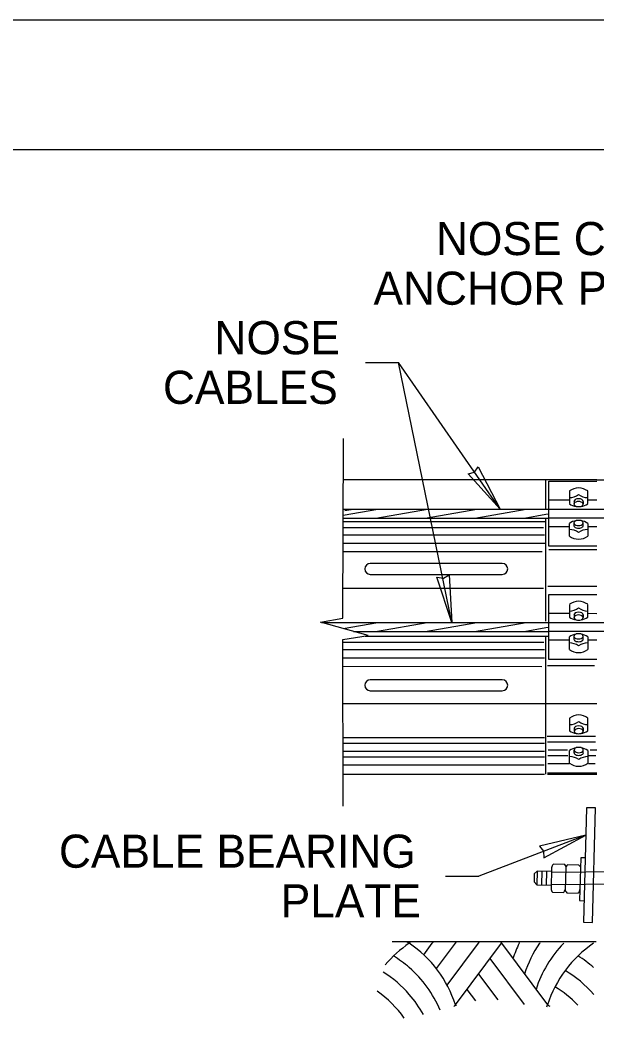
# Model space of a CAD drawing. Extents: x 1312564.2 to 1312581.5, y 1207298.4 to 1207352.6.
# Drawn here: x 1312576.216 to 1312577.61, y 1207335.767 to 1207338.221 of the extents above; entities that cross this region are included whole.
import ezdxf

# ---------------------------------------------------------------- set-up
doc = ezdxf.new("R2010")
doc.units = 0
for name, color, linetype in [('Level 1', 7, 'Continuous'), ('Level 15', 7, 'Continuous'), ('Level 2', 7, 'Continuous'), ('Level 20', 7, 'Continuous'), ('Level 6', 7, 'Continuous')]:
    doc.layers.add(name, color=color, linetype=linetype)

msp = doc.modelspace()

# ---------------------------------------------------------------- linework, layer by layer
at = {"layer": 'Level 1'}
msp.add_line((1312565.4155, 1207337.9084), (1312581.1655, 1207337.9084), dxfattribs=at)
at = {"layer": 'Level 15'}
for p, q in [((1312577.0506, 1207337.393), (1312577.1307, 1207337.393)), ((1312577.2592, 1207336.764), (1312577.1307, 1207337.393)), ((1312577.3766, 1207337.0387), (1312577.1307, 1207337.393)), ((1312577.5832, 1207336.2498), (1312577.3244, 1207336.151)), ((1312577.2443, 1207336.151), (1312577.3244, 1207336.151))]:
    msp.add_line(p, q, dxfattribs=at)
msp.add_lwpolyline([(1312576.9968, 1207336.3197), (1312576.9962, 1207336.723), (1312577.0572, 1207336.7325), (1312576.9417, 1207336.7651), (1312576.9962, 1207336.7749), (1312576.9973, 1207337.2094)], dxfattribs=at)
for points in [[(1312577.3766, 1207337.0387), (1312577.2989, 1207337.1238), (1312577.3141, 1207337.128), (1312577.3233, 1207337.1409)], [(1312577.2592, 1207336.764), (1312577.2232, 1207336.8735), (1312577.2389, 1207336.8711), (1312577.2526, 1207336.8791)], [(1312577.5832, 1207336.2498), (1312577.4711, 1207336.223), (1312577.4814, 1207336.211), (1312577.4818, 1207336.1951)]]:
    msp.add_lwpolyline(points, close=True, dxfattribs=at)
at = {"layer": 'Level 2'}
msp.add_lwpolyline([(1312564.478, 1207327.2209), (1312581.478, 1207327.2209), (1312581.478, 1207338.2209), (1312564.478, 1207338.2209)], close=True, dxfattribs=at)
at = {"layer": 'Level 6'}
for p, q in [((1312577.6098, 1207337.1092), (1312576.997, 1207337.1093)), ((1312577.487, 1207337.0401), (1312577.487, 1207337.1093)), ((1312577.6097, 1207337.1092), (1312577.8224, 1207337.1092)), ((1312577.5438, 1207337.0824), (1312577.5438, 1207337.0663)), ((1312577.5881, 1207337.0663), (1312577.5881, 1207337.0824)), ((1312577.5438, 1207337.0598), (1312577.4939, 1207337.0598)), ((1312577.5438, 1207337.0663), (1312577.5438, 1207337.0517)), ((1312577.5549, 1207337.0571), (1312577.5549, 1207337.0505)), ((1312577.577, 1207337.0571), (1312577.577, 1207337.0505)), ((1312577.5881, 1207337.0517), (1312577.5881, 1207337.0663)), ((1312577.6097, 1207337.0598), (1312577.5881, 1207337.0598)), ((1312576.9968, 1207337.0239), (1312577.0806, 1207337.0387)), ((1312576.9969, 1207337.0387), (1312577.4939, 1207337.0387)), ((1312577.0006, 1207337.0352), (1312577.0208, 1207337.0387)), ((1312577.0755, 1207337.0167), (1312577.2002, 1207337.0387)), ((1312577.1952, 1207337.0167), (1312577.3198, 1207337.0387)), ((1312577.3148, 1207337.0167), (1312577.4395, 1207337.0387)), ((1312577.4939, 1207337.0387), (1312577.9371, 1207337.0387)), ((1312576.9968, 1207337.0167), (1312577.4939, 1207337.0167)), ((1312576.9968, 1207337.0087), (1312577.4859, 1207337.0087)), ((1312577.4344, 1207337.0167), (1312577.487, 1207337.026)), ((1312577.487, 1207337.026), (1312577.4939, 1207337.0272)), ((1312577.487, 1207336.7678), (1312577.487, 1207337.0143)), ((1312577.9371, 1207337.0167), (1312577.4939, 1207337.0167)), ((1312576.9967, 1207336.9937), (1312577.4812, 1207336.9937)), ((1312577.5438, 1207336.9956), (1312577.4939, 1207336.9956)), ((1312577.5438, 1207336.9891), (1312577.5438, 1207337.0038)), ((1312577.5438, 1207336.9731), (1312577.5438, 1207336.9891)), ((1312577.5549, 1207336.9984), (1312577.5549, 1207337.005)), ((1312577.577, 1207336.9984), (1312577.577, 1207337.005)), ((1312577.5881, 1207337.0038), (1312577.5881, 1207336.9891)), ((1312577.6097, 1207336.9956), (1312577.5881, 1207336.9956)), ((1312577.5881, 1207336.9891), (1312577.5881, 1207336.9731)), ((1312576.9967, 1207336.976), (1312577.4832, 1207336.976)), ((1312576.9966, 1207336.9558), (1312577.4842, 1207336.9558)), ((1312577.4779, 1207336.935), (1312576.9966, 1207336.935)), ((1312577.6097, 1207336.94), (1312577.494, 1207336.94)), ((1312577.3814, 1207336.907), (1312577.0623, 1207336.907)), ((1312577.0623, 1207336.8807), (1312577.3814, 1207336.8807)), ((1312577.4808, 1207336.8467), (1312576.9963, 1207336.8468)), ((1312577.6097, 1207336.8511), (1312577.4914, 1207336.8511)), ((1312577.5438, 1207336.8081), (1312577.5438, 1207336.792)), ((1312577.5438, 1207336.792), (1312577.5438, 1207336.7774)), ((1312577.5881, 1207336.792), (1312577.5881, 1207336.8081)), ((1312577.5881, 1207336.7774), (1312577.5881, 1207336.792)), ((1312576.9439, 1207336.7644), (1312577.4939, 1207336.7644)), ((1312576.9964, 1207336.7497), (1312577.0802, 1207336.7644)), ((1312577.0796, 1207336.7432), (1312577.1999, 1207336.7644)), ((1312577.1948, 1207336.7425), (1312577.3195, 1207336.7644)), ((1312577.3144, 1207336.7425), (1312577.4391, 1207336.7644)), ((1312577.5438, 1207336.7856), (1312577.4939, 1207336.7856)), ((1312577.4939, 1207336.7644), (1312577.9371, 1207336.7644)), ((1312577.5549, 1207336.7828), (1312577.5549, 1207336.7762)), ((1312577.577, 1207336.7828), (1312577.577, 1207336.7762)), ((1312577.6097, 1207336.7855), (1312577.5881, 1207336.7856)), ((1312577.0219, 1207336.7425), (1312577.4939, 1207336.7425)), ((1312577.434, 1207336.7425), (1312577.487, 1207336.7518)), ((1312577.487, 1207336.7518), (1312577.4939, 1207336.753)), ((1312577.4939, 1207336.7425), (1312577.4939, 1207336.7425)), ((1312577.9371, 1207336.7425), (1312577.4939, 1207336.7425)), ((1312576.9968, 1207336.7165), (1312577.4822, 1207336.7165)), ((1312577.0502, 1207336.7314), (1312577.4939, 1207336.7314)), ((1312577.487, 1207336.397), (1312577.487, 1207336.7295)), ((1312577.5438, 1207336.7214), (1312577.4939, 1207336.7214)), ((1312577.5438, 1207336.7149), (1312577.5438, 1207336.7295)), ((1312577.5438, 1207336.6988), (1312577.5438, 1207336.7149)), ((1312577.5549, 1207336.7241), (1312577.5549, 1207336.7307)), ((1312577.577, 1207336.7241), (1312577.577, 1207336.7307)), ((1312577.5881, 1207336.7295), (1312577.5881, 1207336.7149)), ((1312577.6097, 1207336.7213), (1312577.5881, 1207336.7214)), ((1312577.5881, 1207336.7149), (1312577.5881, 1207336.6988)), ((1312576.9962, 1207336.6988), (1312577.4832, 1207336.6988)), ((1312576.9962, 1207336.6791), (1312577.4832, 1207336.6791)), ((1312577.4774, 1207336.6573), (1312576.9963, 1207336.6574)), ((1312577.6046, 1207336.6592), (1312577.4908, 1207336.6593)), ((1312577.3814, 1207336.6256), (1312577.0623, 1207336.6256)), ((1312577.0623, 1207336.5993), (1312577.3814, 1207336.5993)), ((1312577.6097, 1207336.5675), (1312576.9964, 1207336.5676)), ((1312577.5441, 1207336.5332), (1312577.5441, 1207336.5171)), ((1312577.5441, 1207336.5171), (1312577.5441, 1207336.5024)), ((1312577.5884, 1207336.5171), (1312577.5884, 1207336.5332)), ((1312577.5884, 1207336.5024), (1312577.5884, 1207336.5171)), ((1312577.5552, 1207336.5079), (1312577.5552, 1207336.5013)), ((1312577.5773, 1207336.5079), (1312577.5773, 1207336.5013)), ((1312577.4832, 1207336.485), (1312576.9966, 1207336.485)), ((1312577.4837, 1207336.4715), (1312576.9966, 1207336.4715)), ((1312577.6069, 1207336.4885), (1312577.4898, 1207336.4885)), ((1312577.6071, 1207336.4747), (1312577.4911, 1207336.4747)), ((1312577.4832, 1207336.4524), (1312576.9966, 1207336.4524)), ((1312577.5395, 1207336.4552), (1312577.492, 1207336.4552)), ((1312577.5441, 1207336.4399), (1312577.5441, 1207336.4546)), ((1312577.5552, 1207336.4491), (1312577.5552, 1207336.4557)), ((1312577.5773, 1207336.4491), (1312577.5773, 1207336.4557)), ((1312577.5884, 1207336.4546), (1312577.5884, 1207336.4399)), ((1312577.6097, 1207336.4551), (1312577.5938, 1207336.4551)), ((1312577.4837, 1207336.4388), (1312576.9966, 1207336.4388)), ((1312577.4823, 1207336.4192), (1312576.9967, 1207336.4192)), ((1312577.5399, 1207336.4418), (1312577.4916, 1207336.4418)), ((1312577.5442, 1207336.4223), (1312577.4916, 1207336.4223)), ((1312577.5441, 1207336.4238), (1312577.5441, 1207336.4399)), ((1312577.5884, 1207336.4399), (1312577.5884, 1207336.4238)), ((1312577.606, 1207336.4223), (1312577.5902, 1207336.4223)), ((1312577.6073, 1207336.4418), (1312577.5907, 1207336.4418)), ((1312576.9967, 1207336.397), (1312577.4832, 1207336.397)), ((1312577.4911, 1207336.4003), (1312577.6097, 1207336.4003)), ((1312577.4911, 1207336.397), (1312577.6097, 1207336.397)), ((1312577.5325, 1207336.1785), (1312577.5049, 1207336.1793)), ((1312577.5669, 1207336.1772), (1312577.5392, 1207336.1779)), ((1312577.4657, 1207336.1628), (1312577.4648, 1207336.1298)), ((1312577.4774, 1207336.1624), (1312577.4765, 1207336.1295)), ((1312577.4884, 1207336.1621), (1312577.4875, 1207336.1292)), ((1312577.5007, 1207336.171), (1312577.4993, 1207336.1205)), ((1312577.5022, 1207336.1607), (1312577.8225, 1207336.1638)), ((1312577.535, 1207336.1696), (1312577.5336, 1207336.1192)), ((1312577.5003, 1207336.1301), (1312577.8228, 1207336.1332)), ((1312577.503, 1207336.112), (1312577.5291, 1207336.1113)), ((1312577.5374, 1207336.1107), (1312577.565, 1207336.1099)), ((1312577.5692, 1207336.1182), (1312577.5693, 1207336.119)), ((1312577.1153, 1207335.9924), (1312577.6087, 1207335.9924)), ((1312577.1564, 1207335.9882), (1312577.1593, 1207335.992)), ((1312577.1914, 1207335.9605), (1312577.2122, 1207335.9882)), ((1312577.2122, 1207335.9882), (1312577.2147, 1207335.9916)), ((1312577.222, 1207335.927), (1312577.2679, 1207335.9882)), ((1312577.2478, 1207335.8871), (1312577.3237, 1207335.9882)), ((1312577.2679, 1207335.9882), (1312577.2701, 1207335.9911)), ((1312577.2679, 1207335.8396), (1312577.3794, 1207335.9882)), ((1312577.3237, 1207335.9882), (1312577.3254, 1207335.9906)), ((1312577.378, 1207335.9902), (1312577.3794, 1207335.9882)), ((1312577.3794, 1207335.9882), (1312577.4909, 1207335.8396)), ((1312577.3515, 1207335.9511), (1312577.4345, 1207335.8404)), ((1312577.3237, 1207335.9139), (1312577.3706, 1207335.8513)), ((1312577.2958, 1207335.8767), (1312577.3168, 1207335.8488)), ((1312577.2646, 1207335.8351), (1312577.2679, 1207335.8396)), ((1312577.2679, 1207335.8396), (1312577.2702, 1207335.8366))]:
    msp.add_line(p, q, dxfattribs=at)
for points in [[(1312577.6097, 1207336.949), (1312577.4939, 1207336.949), (1312577.4939, 1207337.1064), (1312577.6097, 1207337.1063)], [(1312577.6097, 1207336.6747), (1312577.4939, 1207336.6748), (1312577.4939, 1207336.8321), (1312577.6097, 1207336.8321)], [(1312577.5807, 1207336.1951), (1312577.5713, 1207336.1953), (1312577.5685, 1207336.0915), (1312577.5789, 1207336.0912), (1312577.5789, 1207336.092)], [(1312577.5002, 1207336.1618), (1312577.4657, 1207336.1628), (1312577.4589, 1207336.1563), (1312577.4584, 1207336.1366), (1312577.4648, 1207336.1298), (1312577.4996, 1207336.1288)]]:
    msp.add_lwpolyline(points, dxfattribs=at)
msp.add_lwpolyline([(1312577.5996, 1207336.0387), (1312577.6072, 1207336.3156), (1312577.585, 1207336.3162), (1312577.5775, 1207336.0393)], close=True, dxfattribs=at)
for centre, radius, start, end in [((1312577.5663, 1207337.0513), 0.0384, 90.6024, 125.9907), ((1312577.5655, 1207337.0513), 0.0384, 54.0093, 89.3976), ((1312577.5434, 1207337.1047), 0.0384, 270.6024, 305.9907), ((1312577.5885, 1207337.1047), 0.0384, 234.0093, 269.3976), ((1312577.5663, 1207337.0827), 0.0384, 234.0093, 260.5871), ((1312577.5659, 1207337.079), 0.0346, 260.4069, 279.5931), ((1312577.5655, 1207337.0827), 0.0384, 279.4129, 305.9907), ((1312577.5663, 1207336.9727), 0.0384, 99.4129, 125.9907), ((1312577.5659, 1207336.9766), 0.0346, 80.4069, 99.5931), ((1312577.5655, 1207336.9727), 0.0384, 54.0093, 80.5871), ((1312577.5434, 1207336.9508), 0.0384, 54.0093, 89.3976), ((1312577.5885, 1207336.9508), 0.0384, 90.6024, 125.9907), ((1312577.5663, 1207337.0041), 0.0384, 234.0093, 269.3976), ((1312577.5655, 1207337.0041), 0.0384, 270.6024, 305.9907), ((1312577.0623, 1207336.8938), 0.0132, 90, 270), ((1312577.3814, 1207336.8938), 0.0132, 270, 90), ((1312577.5663, 1207336.7771), 0.0384, 90.6024, 125.9907), ((1312577.5655, 1207336.7771), 0.0384, 54.0093, 89.3976), ((1312577.5434, 1207336.8304), 0.0384, 270.6024, 305.9907), ((1312577.5885, 1207336.8304), 0.0384, 234.0093, 269.3976), ((1312577.5663, 1207336.8085), 0.0384, 234.0093, 260.5871), ((1312577.5659, 1207336.8047), 0.0346, 260.4069, 279.5931), ((1312577.5655, 1207336.8085), 0.0384, 279.4129, 305.9907), ((1312577.5663, 1207336.6985), 0.0384, 99.4129, 125.9907), ((1312577.5434, 1207336.6765), 0.0384, 54.0093, 89.3976), ((1312577.5659, 1207336.7024), 0.0346, 80.4069, 99.5931), ((1312577.5885, 1207336.6765), 0.0384, 90.6024, 125.9907), ((1312577.5655, 1207336.6985), 0.0384, 54.0093, 80.5871), ((1312577.5663, 1207336.7299), 0.0384, 234.0093, 269.3976), ((1312577.5655, 1207336.7299), 0.0384, 270.6024, 305.9907), ((1312577.0623, 1207336.6125), 0.0132, 90, 270), ((1312577.3814, 1207336.6125), 0.0132, 270, 90), ((1312577.5667, 1207336.5021), 0.0384, 90.6024, 125.9907), ((1312577.5437, 1207336.5555), 0.0384, 270.6024, 305.9907), ((1312577.5658, 1207336.5021), 0.0384, 54.0093, 89.3976), ((1312577.5888, 1207336.5555), 0.0384, 234.0093, 269.3976), ((1312577.5667, 1207336.5335), 0.0384, 234.0093, 260.5871), ((1312577.5662, 1207336.5298), 0.0346, 260.4069, 279.5931), ((1312577.5658, 1207336.5335), 0.0384, 279.4129, 305.9907), ((1312577.5667, 1207336.4235), 0.0384, 99.4129, 125.9907), ((1312577.5662, 1207336.4274), 0.0346, 80.4069, 99.5931), ((1312577.5658, 1207336.4235), 0.0384, 54.0093, 80.5871), ((1312577.5437, 1207336.4015), 0.0384, 54.0093, 89.3976), ((1312577.5667, 1207336.4549), 0.0384, 234.0093, 269.3976), ((1312577.5888, 1207336.4015), 0.0384, 90.6024, 125.9907), ((1312577.5658, 1207336.4549), 0.0384, 270.6024, 305.9907), ((1312577.5116, 1207336.1707), 0.0109, 128.0406, 178.4426), ((1312577.5254, 1207336.1703), 0.0109, 21.9491, 48.8451), ((1312577.5459, 1207336.1693), 0.0109, 128.0406, 178.4426), ((1312577.5597, 1207336.1689), 0.0109, 21.9491, 48.8451), ((1312577.5102, 1207336.1202), 0.0109, 178.4432, 228.8451), ((1312577.5218, 1207336.1208), 0.012, 308.0505, 349.8518), ((1312577.5445, 1207336.1189), 0.0109, 178.4432, 228.8451), ((1312577.5583, 1207336.1185), 0.0109, 308.0406, 349.8419), ((1312577.3138, 1207335.7541), 0.2821, 123.9036, 139.7607), ((1312577.3138, 1207336.2224), 0.2821, 234.7075, 236.0964), ((1312576.9991, 1207335.7541), 0.2821, 17.6434, 56.0963), ((1312577.6482, 1207335.9027), 0.2821, 161.9487, 162.3566), ((1312577.6761, 1207335.8656), 0.2821, 154.2265, 162.3566), ((1312577.6761, 1207335.8656), 0.2821, 153.8779, 154.2266), ((1312577.704, 1207335.8284), 0.2821, 145.491, 162.3566), ((1312577.7318, 1207335.7912), 0.2821, 135.7127, 162.3566), ((1312577.704, 1207335.8284), 0.2821, 145.215, 145.4911), ((1312577.7597, 1207335.7541), 0.2821, 123.9045, 162.3566), ((1312577.7318, 1207335.7912), 0.2821, 135.5372, 135.7128), ((1312576.9712, 1207335.7169), 0.2821, 48.9597, 58.5465), ((1312577.4171, 1207335.7169), 0.2821, 48.9608, 58.5465), ((1312576.9712, 1207335.7169), 0.2821, 22.8342, 48.9597), ((1312576.9434, 1207335.6798), 0.2821, 40.9413, 57.9177), ((1312577.3893, 1207335.6798), 0.2821, 40.9426, 59.3021), ((1312577.3614, 1207335.6426), 0.2821, 44.0924, 58.4874), ((1312576.9155, 1207335.6426), 0.2821, 35.7138, 54.5211), ((1312576.9434, 1207335.6798), 0.2821, 28.8216, 40.9414), ((1312577.222, 1207335.9251), 0.2821, 341.3302, 342.3566), ((1312577.3335, 1207335.6054), 0.2821, 54.5374, 56.0964)]:
    msp.add_arc(centre, radius, start, end, dxfattribs=at)
for centre, start_param, end_param in [((1312577.5659, 1207337.0505), 2.23043, 7.194348), ((1312577.5659, 1207337.0571), 3.141593, 6.283185), ((1312577.5659, 1207337.005), 5.372022, 10.335941), ((1312577.5659, 1207336.9984), 0, 3.141593), ((1312577.5659, 1207336.7828), 3.141593, 6.283185), ((1312577.5659, 1207336.7762), 2.23043, 7.194348), ((1312577.5659, 1207336.7307), 5.372022, 10.335941), ((1312577.5659, 1207336.7241), 0, 3.141593), ((1312577.5663, 1207336.5013), 2.23043, 7.194348), ((1312577.5663, 1207336.5079), 3.141593, 6.283185), ((1312577.5663, 1207336.4557), 5.372022, 10.335941), ((1312577.5663, 1207336.4491), 0, 3.141593)]:
    msp.add_ellipse(centre, major_axis=(-0.0111, 0), ratio=0.572704, start_param=start_param, end_param=end_param, dxfattribs=at)

# ---------------------------------------------------------------- texts
at = {"layer": 'Level 20'}
for s, height, p in [('NOSE CABLE', 0.08008, (1312577.221, 1207337.6529)), ('ANCHOR PLATE', 0.080077, (1312577.07, 1207337.5328)), ('NOSE', 0.08008, (1312576.6854, 1207337.4131)), (' CABLES', 0.08008, (1312576.5312, 1207337.293)), ('CABLE BEARING', 0.080077, (1312576.3094, 1207336.171)), ('PLATE', 0.08008, (1312576.8457, 1207336.0509))]:
    msp.add_text(s, height=height, dxfattribs=at).set_placement(p)

doc.saveas('drawing.dxf')
